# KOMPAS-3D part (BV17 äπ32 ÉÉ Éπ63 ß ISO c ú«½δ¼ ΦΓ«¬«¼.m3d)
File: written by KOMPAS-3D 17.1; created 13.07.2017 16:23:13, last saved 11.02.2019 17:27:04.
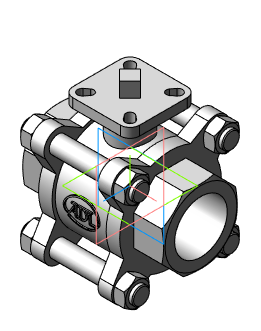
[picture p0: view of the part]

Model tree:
1. Операция без истории:2  (labels: Сталь 20  ГОСТ 1050-88)

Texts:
  DISO1
  DISO2
  BV17 Ду8 1/4" Ру63 с ISO
  BV17 Ду8 СС Ру63 с ISO
  BV17 Ду10 3/8" Ру63 с ISO
  BV17 Ду10 СС Ру63 с ISO
  BV17 Ду15 1/2" Ру63 с ISO
  BV17 Ду15 СС Ру63 с ISO
  BV17 Ду15 ФФ Ру40 с ISO
  BV17 Ду20 3/4" Ру63 с ISO
  BV17 Ду20 СС Ру40 с ISO
  BV17 Ду20 ФФ Ру40 с ISO
  BV17 Ду25 1" Ру63 с ISO
  BV17 Ду25 СС Ру63 с ISO
  BV17 Ду25 ФФ Ру40 с ISO
  BV17 Ду32 1 1/4" Ру63 с ISO
  BV17 Ду32 СС Ру63 с ISO
  BV17 Ду32 ФФ Ру40 с ISO
  BV17 Ду40 1 1/2" Ру63 с ISO
  BV17 Ду40 СС Ру63 с ISO
  BV17 Ду40 ФФ Ру40 с ISO
  BV17 Ду50 2" Ру63 с ISO
  BV17 Ду50 СС Ру63 с ISO
  BV17 Ду50 ФФ Ру40 с ISO
  BV17 Ду65 2 1/2" Ру40 с ISO
  BV17 Ду65 СС Ру40 с ISO
  BV17 Ду65 ФФ Ру40 с ISO
  BV17 Ду80 3" Ру40 с ISO
  BV17 Ду80 СС Ру40 с ISO
  BV17 Ду80 ФФ Ру40 с ISO
  BV17 Ду100 4" Ру40 с ISO
  BV17 Ду100 СС Ру40 с ISO
  BV17 Ду100 ФФ Ру40 с ISO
